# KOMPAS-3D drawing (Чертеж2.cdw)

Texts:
  Стандартные изделия
  Болт М10x1,25-6gx30.109.30ХГСА (S16) ГОСТ 7805-70
  Гайка  М10x1,25-6H.04 (S16) ГОСТ 5915-70
  Шайба 10Л БрКМц3-1 ГОСТ 6402-70
  Болт М10x1,25-6gx35.109.30ХГСА (S16) ГОСТ 7805-70
  Болт М18x1,5-6gx20.109.30ХГСА ГОСТ 7805-70
Dimensions and other numbers on the sheet: 8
